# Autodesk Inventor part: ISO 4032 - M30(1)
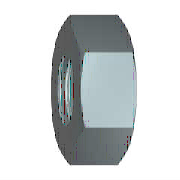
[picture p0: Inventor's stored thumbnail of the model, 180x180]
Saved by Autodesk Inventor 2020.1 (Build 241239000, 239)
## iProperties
Created: 2019-01
Part Number: ISO 4032 - M30(1)
Material: Edelstahl, 440C
Description: Sechskantmutter
Document SubType Name: Modeling
Standard: ISO 4032
Designer: lutzd
Standards Organization: DIN
Language: de-DE
Size Designation: M30
Categories: <MemberInstance><Categories><Category DisplayName="Verbindungselemente" InternalName="e4da775c-781d-43d5-af7c-5136215cf5a6" Mnemonic="FSTN"><Category DisplayNam
Mass: 249.433 g
Surface Area: 82.477 cm^2
Volume: 32.185 cm^3
Density: 7.75 g/cm^3
Appearance: Halbpoliert
IsCustomPart: 0
Author: lutzd
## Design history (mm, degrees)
body "Solid1"
sketch "Skizze1"
  geometry: L1 (-26.558, 0)-(-13.279, 23); L2 (-13.279, 23)-(13.279, 23); L3 (13.279, 23)-(26.558, 0); L4 (26.558, 0)-(13.279, -23); L5 (13.279, -23)-(-13.279, -23); L6 (-13.279, -23)-(-26.558, 0); 2 further points
  constraints: 12 end point, 1 coincident, 1 horizontal, 11 other
  dimensions: "d0" = 53.11622 distance of L3.end L1.start (= 1.1547 x SW)
workaxis "Work Axis1"
workplane "Work Plane1"
extrude "Körper" new body sketch "Skizze1" distance "d1" = 25.6 (= KOH); taper "d2" = 0 deg
sketch "Skizze2"
  geometry: L1 (0, 13.279)-(0, 26.558) reference; L2 (0, 26.558)-(25.6, 26.558) reference; L3 (25.6, 13.279)-(25.6, 26.558) reference; L4 (-5.12, 0)-(30.72, 0) reference; L5 (2.978, 26.558)-(0, 21.4); L6 (22.622, 26.558)-(25.6, 21.4)
  constraints: 4 end point, 4 point on line
  dimensions: "d3" = 30 deg angle of L1 L5 (= ANG1); "d4" = 30 deg angle of L3 L6 (= ANG2); "d5" = 42.8 diameter of L5.end L4 (= SW0); "d6" = 42.8 diameter of L6.end L4 (= SW01)
revolve "Fase1" stored, may be unused: angle "d7" = 90 deg
sketch "Skizze3"
  geometry: 4 further points
  constraints: 1 coincident, 1 other
hole "Gewinde" sketch "Skizze3" diameter "d25" = 26.211; stored, may be unused: countersink angle "d29" = 82 deg, drill point angle "d31" = 118 deg; dims "d26" = 6, "d27" = 4, "d28" = 2, "d30" = 8
chamfer "Fase2" distance "d8" = 1.89443 (= -0.5 x GD1 + 0.5 x NND); stored, may be unused: angle "d9" = 30 deg, second distance "d40" = 1.89443 (= -0.5 x GD1 + 0.5 x NND)
chamfer "Fase3" distance "d10" = 1.89443 (= -0.5 x GD1 + 0.5 x NND); stored, may be unused: angle "d11" = 30 deg, second distance "d41" = 1.89443 (= -0.5 x GD1 + 0.5 x NND)
other parameters: "ANG1" = 30 deg [user parameter; used in 1 equation term], "ANG2" = 30 deg [user parameter; used in 1 equation term], "KOH" = 25.6 [user parameter; used in 1 equation term], "SW" = 46 [user parameter; used in 2 equation terms], "SW0" = 42.8 [user parameter; used in 1 equation term], "SW01" = 42.8 [user parameter; used in 1 equation term], "GD1" = 26.21114 (computed from THREADDIA, PTC, TOA) [user parameter; used in 4 equation terms], "d13" = 0, "d14" = 0, "d39" = 0, "d42" = 0, "GUL" = 1.89443 (= 0.541266 x PTC) [user parameter], "TPU" = 2.85714 (computed from PTC) [user parameter], "TOA" = 30 deg [user parameter; used in 1 equation term], "PTC" = 3.5 [user parameter; used in 4 equation terms], "E0" = 53.13 (= 1.155 x SW) [user parameter], "GAL" = 1.89443 (= 0.541266 x PTC) [user parameter]
